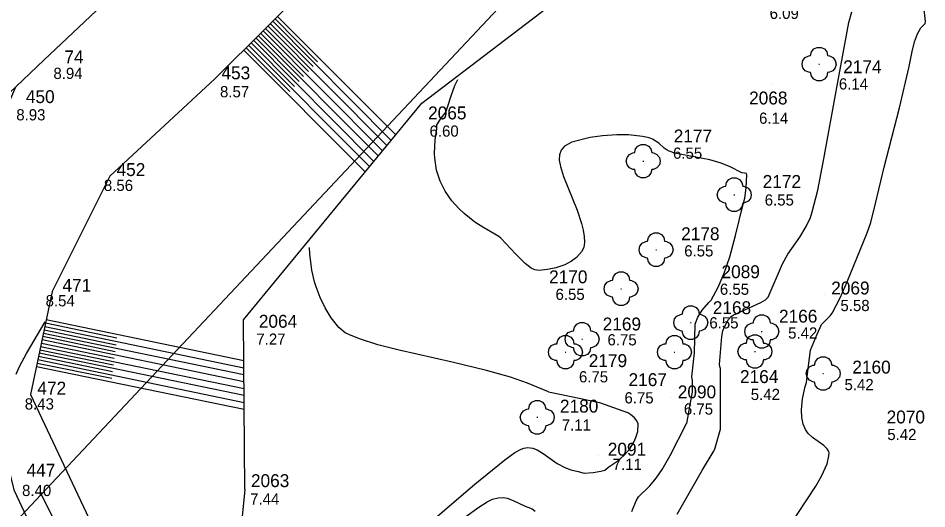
# Model space of a CAD drawing. Extents: x -792549 to -792339, y -1111914 to -1111617.
# Drawn here: x -792457.02 to -792430.26, y -1111722.5 to -1111708.04 of the extents above; entities that cross this region are included whole.
import ezdxf

# ---------------------------------------------------------------- set-up
doc = ezdxf.new("R2010")
doc.units = 0
for name, color, linetype in [('Vrstva 1', 7, 'Continuous'), ('Vrstva 32', 7, 'Continuous'), ('Vrstva 33', 7, 'Continuous'), ('Vrstva 41', 7, 'Continuous'), ('Vrstva 44', 7, 'Continuous'), ('Vrstva 46', 7, 'Continuous'), ('Vrstva 47', 7, 'Continuous'), ('Vrstva 48', 7, 'Continuous'), ('Vrstva 49', 7, 'Continuous'), ('Vrstva 50', 7, 'Continuous'), ('Vrstva 52', 7, 'Continuous'), ('Vrstva 54', 7, 'Continuous')]:
    doc.layers.add(name, color=color, linetype=linetype)

# ---------------------------------------------------------------- blocks, each defined once
blk = doc.blocks.new('SC6231')
at = {"layer": 'Vrstva 1'}
blk.add_line((0, 0), (0, 0), dxfattribs=at)
blk = doc.blocks.new('3$1301')
at = {"layer": 'Vrstva 1'}
for points in [[(20, 0), (19, -4.3), (16.2, -7.8), (12.2, -9.7), (10, -10), (9, -14.3), (6.2, -17.8), (2.2, -19.7), (-2.3, -19.7), (-6.3, -17.8), (-9.1, -14.3), (-10.1, -10), (-12.3, -9.7), (-16.3, -7.8), (-19.1, -4.3), (-20.1, 0), (-19.1, 4.3), (-16.3, 7.8), (-12.3, 9.7), (-10.1, 10), (-9.1, 14.3), (-6.3, 17.8), (-2.3, 19.7), (2.2, 19.7), (6.2, 17.8), (9, 14.3), (10, 10), (12.2, 9.7), (16.2, 7.8), (19, 4.3), (20, 0)], [(-0.5, 0), (0, 0), (0.5, 0)]]:
    blk.add_lwpolyline(points, dxfattribs=at)

msp = doc.modelspace()

# ---------------------------------------------------------------- linework, layer by layer
at = {"layer": 'Vrstva 32'}
for points in [[(-792436.345, -1111718.343), (-792436.36, -1111718.24), (-792436.298, -1111717.419), (-792436.269, -1111717.247), (-792436.219, -1111717.131), (-792436.1, -1111716.914), (-792436.017, -1111716.827), (-792435.958, -1111716.792), (-792435.152, -1111716.421), (-792435.005, -1111716.333), (-792434.935, -1111716.263), (-792434.51, -1111715.273), (-792434.353, -1111714.997), (-792433.997, -1111714.492), (-792433.81, -1111714.173), (-792433.688, -1111713.911), (-792433.631, -1111713.748), (-792433.471, -1111713.104), (-792433.289, -1111712.18), (-792432.912, -1111710.081), (-792432.553, -1111708.169), (-792432.465, -1111707.848)], [(-792441.4, -1111719.047), (-792442.019, -1111718.793), (-792442.52, -1111718.62), (-792443.225, -1111718.418), (-792444.232, -1111718.176), (-792445.794, -1111717.823), (-792446.426, -1111717.66), (-792446.963, -1111717.491), (-792447.275, -1111717.362), (-792447.387, -1111717.309), (-792447.571, -1111717.151), (-792447.796, -1111716.87), (-792447.979, -1111716.578), (-792448.127, -1111716.273), (-792448.245, -1111715.954), (-792448.289, -1111715.811), (-792448.37, -1111715.464), (-792448.432, -1111714.983), (-792448.44, -1111714.795)], [(-792436.345, -1111718.343), (-792436.345, -1111718.879), (-792436.345, -1111719.519), (-792436.345, -1111720.159), (-792436.526, -1111720.779)], [(-792441.4, -1111719.047), (-792440.682, -1111719.201), (-792439.901, -1111719.367), (-792439.076, -1111719.658)], [(-792444.728, -1111722.762), (-792443.57, -1111721.773), (-792442.689, -1111721.057), (-792442.391, -1111720.839), (-792442.209, -1111720.736), (-792442.13, -1111720.706), (-792442.008, -1111720.686), (-792441.861, -1111720.704), (-792441.735, -1111720.754), (-792441.555, -1111720.864), (-792441.146, -1111721.159), (-792440.921, -1111721.282), (-792440.742, -1111721.348), (-792440.529, -1111721.392), (-792440.345, -1111721.448), (-792440.085, -1111721.43), (-792439.857, -1111721.391), (-792439.742, -1111721.359), (-792439.627, -1111721.257), (-792439.359, -1111721.082), (-792439.19, -1111720.938), (-792439.028, -1111720.756), (-792438.89, -1111720.533), (-792438.824, -1111720.391), (-792438.769, -1111720.213), (-792438.76, -1111719.993), (-792438.796, -1111719.9), (-792438.863, -1111719.812), (-792438.983, -1111719.714), (-792439.076, -1111719.658)], [(-792437.613, -1111722.656), (-792436.861, -1111721.351), (-792436.526, -1111720.779)]]:
    msp.add_lwpolyline(points, dxfattribs=at)
at = {"layer": 'Vrstva 33'}
for points in [[(-792433.356, -1111717.067), (-792433.11, -1111716.809), (-792433.045, -1111716.731), (-792432.813, -1111716.275), (-792432.608, -1111715.803), (-792432.012, -1111714.361), (-792431.911, -1111714.061), (-792431.77, -1111713.504), (-792431.519, -1111712.433), (-792431.065, -1111710.681), (-792430.779, -1111709.459), (-792430.691, -1111709.016), (-792430.621, -1111708.735), (-792430.531, -1111708.502), (-792430.432, -1111708.324), (-792430.312, -1111708.195), (-792430.298, -1111708.14), (-792430.408, -1111707.169)], [(-792437.174, -1111718.69), (-792437.176, -1111718.608), (-792437.102, -1111717.896), (-792437.08, -1111717.059), (-792437.072, -1111717.021), (-792437.006, -1111716.851), (-792436.872, -1111716.639), (-792436.682, -1111716.412), (-792436.612, -1111716.344), (-792436.404, -1111715.962), (-792436.229, -1111715.553), (-792436.061, -1111715.068), (-792435.891, -1111714.445), (-792435.678, -1111713.562), (-792435.615, -1111713.345), (-792435.577, -1111713.038), (-792435.558, -1111712.65), (-792435.57, -1111712.618), (-792435.627, -1111712.606), (-792435.711, -1111712.599), (-792436.048, -1111712.418), (-792436.311, -1111712.313), (-792436.652, -1111712.215), (-792437.684, -1111712.013), (-792437.849, -1111711.956), (-792437.908, -1111711.928), (-792437.989, -1111711.865), (-792438.148, -1111711.719), (-792438.335, -1111711.607), (-792438.439, -1111711.562), (-792438.63, -1111711.521), (-792439.049, -1111711.479), (-792439.383, -1111711.472), (-792439.806, -1111711.503), (-792440.169, -1111711.552), (-792440.708, -1111711.693), (-792440.931, -1111711.812), (-792441.03, -1111711.924), (-792441.078, -1111712.061), (-792441.084, -1111712.222), (-792441.051, -1111712.409), (-792440.957, -1111712.704), (-792440.559, -1111713.699), (-792440.428, -1111714.085), (-792440.378, -1111714.285), (-792440.348, -1111714.47), (-792440.34, -1111714.64), (-792440.363, -1111714.792), (-792440.429, -1111714.922), (-792440.576, -1111715.091), (-792440.721, -1111715.202), (-792440.923, -1111715.305), (-792441.184, -1111715.395), (-792441.43, -1111715.448), (-792441.685, -1111715.469), (-792441.804, -1111715.457), (-792441.911, -1111715.405), (-792442.084, -1111715.265), (-792442.358, -1111714.989), (-792442.799, -1111714.518), (-792442.86, -1111714.469), (-792443.33, -1111714.2), (-792443.567, -1111714.045), (-792443.886, -1111713.793), (-792444.043, -1111713.647), (-792444.25, -1111713.418), (-792444.444, -1111713.136), (-792444.592, -1111712.837), (-792444.697, -1111712.516), (-792444.75, -1111712.162), (-792444.759, -1111712.023), (-792444.741, -1111711.621), (-792444.685, -1111711.298), (-792444.689, -1111711.198), (-792444.684, -1111711.178), (-792444.585, -1111711.018), (-792444.457, -1111710.85), (-792444.418, -1111710.782), (-792444.364, -1111710.634), (-792444.27, -1111710.329), (-792444.155, -1111710.02), (-792444.072, -1111709.85)], [(-792457.077, -1111718.53), (-792456.981, -1111718.301), (-792456.77, -1111717.924), (-792456.221, -1111716.99)], [(-792433.802, -1111718.771), (-792433.753, -1111718.359), (-792433.688, -1111717.825), (-792433.489, -1111717.35), (-792433.356, -1111717.067)], [(-792437.174, -1111718.69), (-792437.174, -1111719.058), (-792437.234, -1111719.42), (-792437.339, -1111719.984)], [(-792434.338, -1111723.068), (-792433.526, -1111721.824), (-792433.356, -1111721.536), (-792433.19, -1111721.174), (-792433.14, -1111720.931), (-792433.139, -1111720.85), (-792433.149, -1111720.807), (-792433.192, -1111720.726), (-792433.288, -1111720.634), (-792433.623, -1111720.396), (-792433.75, -1111720.273), (-792433.828, -1111720.163), (-792433.901, -1111720), (-792433.944, -1111719.804), (-792433.954, -1111719.575), (-792433.925, -1111719.26), (-792433.839, -1111718.896), (-792433.802, -1111718.771)], [(-792438.946, -1111722.58), (-792438.821, -1111722.259), (-792438.746, -1111722.147), (-792438.419, -1111721.823), (-792438.228, -1111721.596), (-792438.051, -1111721.338), (-792437.817, -1111720.925), (-792437.339, -1111719.984)], [(-792443.839, -1111722.722), (-792443.452, -1111722.443), (-792443.202, -1111722.289), (-792443.052, -1111722.216), (-792442.881, -1111722.169), (-792442.739, -1111722.164), (-792442.615, -1111722.186), (-792442.444, -1111722.248), (-792442.086, -1111722.414), (-792441.88, -1111722.492), (-792441.791, -1111722.563)]]:
    msp.add_lwpolyline(points, dxfattribs=at)
at = {"layer": 'Vrstva 41'}
msp.add_line((-792456.34, -1111722.07), (-792402.71, -1111664.98), dxfattribs=at)
msp.add_lwpolyline([(-792444.71, -1111766.33), (-792434.44, -1111743.01), (-792441.66, -1111747.03), (-792441.97, -1111752.1), (-792445.31, -1111753.45), (-792459.79, -1111725.74), (-792456.34, -1111722.07), (-792447.22, -1111740.16), (-792434.96, -1111737.57), (-792416.43, -1111722.62), (-792397.39, -1111711.98), (-792389.29, -1111709.91)], dxfattribs=at)
at = {"layer": 'Vrstva 46'}
msp.add_line((-792450.34, -1111721.93), (-792450.98, -1111728.02), dxfattribs=at)
for points in [[(-792424.32, -1111681.62), (-792428.6, -1111686.8), (-792432.83, -1111691.26), (-792437.19, -1111695.67), (-792442.24, -1111700.64), (-792446.68, -1111705.3), (-792451.23, -1111709.83), (-792454.32, -1111712.69), (-792456.02, -1111716.09), (-792456.65, -1111719.13), (-792454.6, -1111723.48), (-792450.98, -1111728.02)], [(-792450.34, -1111721.93), (-792450.38, -1111716.93), (-792445.13, -1111710.54), (-792438.2, -1111705.25), (-792433.41, -1111700.19), (-792426.56, -1111695.49), (-792423.34, -1111689.49), (-792419.98, -1111686.63)]]:
    msp.add_lwpolyline(points, dxfattribs=at)
at = {"layer": 'Vrstva 47'}
msp.add_lwpolyline([(-792409.31, -1111719.38), (-792418.34, -1111725.56), (-792424.82, -1111730.4), (-792430.22, -1111734.34), (-792434.41, -1111737.13), (-792442.38, -1111740.78), (-792445.75, -1111740.01), (-792449.54, -1111736.26), (-792452.26, -1111731.65), (-792454.7, -1111727.15), (-792457.13, -1111721.97), (-792458.5, -1111716.6), (-792458.46, -1111713.25), (-792457.09, -1111710.06)], dxfattribs=at)
at = {"layer": 'Vrstva 52'}
msp.add_lwpolyline([(-792463.52, -1111716.12), (-792462.35, -1111715.02), (-792457.09, -1111710.06), (-792456.25, -1111709.27), (-792447.6, -1111701.1), (-792439.97, -1111693.46), (-792433.2, -1111686.44), (-792426.83, -1111679.83)], dxfattribs=at)
at = {"layer": 'Vrstva 54'}
for p, q in [((-792449.38, -1111707.99), (-792445.9, -1111711.48)), ((-792449.66, -1111708.27), (-792446.16, -1111711.79)), ((-792449.59, -1111708.2), (-792448.33, -1111709.46)), ((-792449.52, -1111708.13), (-792446.03, -1111711.64)), ((-792449.45, -1111708.06), (-792448.2, -1111709.32)), ((-792449.95, -1111708.55), (-792446.41, -1111712.1)), ((-792449.88, -1111708.48), (-792448.61, -1111709.76)), ((-792449.8, -1111708.41), (-792446.29, -1111711.95)), ((-792449.73, -1111708.34), (-792448.47, -1111709.61)), ((-792450.23, -1111708.83), (-792446.67, -1111712.41)), ((-792450.16, -1111708.76), (-792448.88, -1111710.05)), ((-792450.09, -1111708.69), (-792446.54, -1111712.26)), ((-792450.02, -1111708.62), (-792448.74, -1111709.9)), ((-792450.37, -1111708.98), (-792446.8, -1111712.57)), ((-792450.3, -1111708.91), (-792449.02, -1111710.2)), ((-792456.23, -1111717.12), (-792450.37, -1111718.34)), ((-792456.21, -1111717.02), (-792454.11, -1111717.46)), ((-792456.19, -1111716.92), (-792450.37, -1111718.13)), ((-792456.27, -1111717.32), (-792450.37, -1111718.54)), ((-792456.25, -1111717.22), (-792454.13, -1111717.66)), ((-792456.33, -1111717.61), (-792454.19, -1111718.06)), ((-792456.31, -1111717.51), (-792450.37, -1111718.74)), ((-792456.29, -1111717.41), (-792454.16, -1111717.86)), ((-792456.4, -1111717.9), (-792450.36, -1111719.15)), ((-792456.38, -1111717.81), (-792454.21, -1111718.25)), ((-792456.36, -1111717.71), (-792450.36, -1111718.95)), ((-792456.46, -1111718.2), (-792454.26, -1111718.65)), ((-792456.44, -1111718.1), (-792450.36, -1111719.36)), ((-792456.42, -1111718), (-792454.24, -1111718.45)), ((-792456.48, -1111718.3), (-792450.36, -1111719.56))]:
    msp.add_line(p, q, dxfattribs=at)

# ---------------------------------------------------------------- block references
at = {"layer": 'Vrstva 44', "xscale": 0.025, "yscale": 0.025000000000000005}
for p in [(-792433.43, -1111709.39), (-792438.61, -1111712.25), (-792435.93, -1111713.24), (-792438.23, -1111714.86), (-792439.26, -1111716.01), (-792437.21, -1111717.01), (-792435.12, -1111717.27), (-792440.41, -1111717.5), (-792440.9, -1111717.88), (-792437.69, -1111717.88), (-792435.32, -1111717.86), (-792433.31, -1111718.51), (-792441.73, -1111719.8)]:
    msp.add_blockref('3$1301', p, dxfattribs=at)
at = {"layer": 'Vrstva 48', "xscale": 0.1, "yscale": 0.10000000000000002}
for p in [(-792456.25, -1111709.27), (-792433.43, -1111709.39), (-792451.23, -1111709.83), (-792434.81, -1111710), (-792445.13, -1111710.54), (-792438.61, -1111712.25), (-792454.32, -1111712.69), (-792435.93, -1111713.24), (-792438.23, -1111714.86), (-792439.26, -1111716.01), (-792456.02, -1111716.09), (-792433.27, -1111716.18), (-792436.81, -1111716.34), (-792450.38, -1111716.93), (-792437.21, -1111717.01), (-792435.12, -1111717.27), (-792440.41, -1111717.5), (-792440.9, -1111717.88), (-792437.69, -1111717.88), (-792435.32, -1111717.86), (-792433.31, -1111718.51), (-792456.65, -1111719.13), (-792437.77, -1111719.23), (-792441.73, -1111719.8), (-792431.62, -1111719.97), (-792439.94, -1111720.93), (-792450.34, -1111721.93)]:
    msp.add_blockref('SC6231', p, dxfattribs=at)

# ---------------------------------------------------------------- texts
at = {"layer": 'Vrstva 49'}
for s, p in [('74', (-792455.658, -1111709.37)), ('2174', (-792432.721, -1111709.66)), ('453', (-792451.031, -1111709.84)), ('450', (-792456.791, -1111710.54)), ('2068', (-792435.493, -1111710.58)), ('2065', (-792444.946, -1111711.02)), ('2177', (-792437.713, -1111711.7)), ('452', (-792454.121, -1111712.69)), ('2172', (-792435.093, -1111713.04)), ('2178', (-792437.493, -1111714.58)), ('2170', (-792441.383, -1111715.85)), ('2089', (-792436.305, -1111715.7)), ('471', (-792455.713, -1111716.1)), ('2069', (-792433.075, -1111716.18)), ('2168', (-792436.563, -1111716.76)), ('2064', (-792449.931, -1111717.16)), ('2169', (-792439.805, -1111717.24)), ('2166', (-792434.613, -1111717.01)), ('2179', (-792440.215, -1111718.32)), ('2160', (-792432.453, -1111718.51)), ('2164', (-792435.761, -1111718.79)), ('2167', (-792439.043, -1111718.88)), ('472', (-792456.451, -1111719.13)), ('2090', (-792437.593, -1111719.24)), ('2180', (-792441.063, -1111719.66)), ('2070', (-792431.443, -1111719.98)), ('2091', (-792439.655, -1111720.93)), ('447', (-792456.771, -1111721.55)), ('2063', (-792450.163, -1111721.856))]:
    msp.add_text(s, height=0.38, dxfattribs=at).set_placement(p)
at = {"layer": 'Vrstva 50'}
for s, p in [('6.09', (-792434.887, -1111708.06)), ('8.94', (-792455.979, -1111709.83)), ('6.14', (-792432.849, -1111710.14)), ('8.57', (-792451.073, -1111710.37)), ('8.93', (-792457.073, -1111711.05)), ('6.14', (-792435.199, -1111711.15)), ('6.60', (-792444.903, -1111711.53)), ('6.55', (-792437.733, -1111712.18)), ('8.56', (-792454.493, -1111713.13)), ('6.55', (-792435.033, -1111713.56)), ('6.55', (-792437.403, -1111715.06)), ('6.55', (-792441.193, -1111716.34)), ('6.55', (-792436.353, -1111716.19)), ('8.54', (-792456.209, -1111716.53)), ('5.58', (-792432.803, -1111716.67)), ('6.55', (-792436.663, -1111717.18)), ('7.27', (-792450.003, -1111717.66)), ('6.75', (-792439.663, -1111717.68)), ('5.42', (-792434.343, -1111717.48)), ('6.75', (-792440.503, -1111718.77)), ('5.42', (-792432.683, -1111719)), ('5.42', (-792435.443, -1111719.29)), ('8.43', (-792456.823, -1111719.57)), ('6.75', (-792439.163, -1111719.39)), ('6.75', (-792437.413, -1111719.72)), ('7.11', (-792441.009, -1111720.19)), ('5.42', (-792431.423, -1111720.47)), ('7.11', (-792439.509, -1111721.35)), ('8.40', (-792456.903, -1111722.12)), ('7.44', (-792450.186, -1111722.37))]:
    msp.add_text(s, height=0.33, dxfattribs=at).set_placement(p)

doc.saveas('drawing.dxf')
